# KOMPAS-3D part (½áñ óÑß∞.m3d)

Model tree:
1. Эскиз:1
2. Операция выдавливания:1
     Расстояние 1 = 20
3. Эскиз:2
4. Операция выдавливания:2
     Расстояние 1 = 400
5. Эскиз:3
6. Вырезать элемент выдавливания:1
     Расстояние 1 = 70
7. Эскиз:4
8. Вырезать элемент выдавливания:2
     Расстояние 1 = 2
9. Эскиз:5
10. Эскиз:11
11. Вырезать элемент выдавливания:7
     Расстояние 1 = 30
